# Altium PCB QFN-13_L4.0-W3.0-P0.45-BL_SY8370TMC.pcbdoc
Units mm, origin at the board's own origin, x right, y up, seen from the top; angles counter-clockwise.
Board outline 17.4 x 16.65 mm, 2 copper layers (Top Layer, Bottom Layer), stack 0 mm thick; 1 components, 0 nets, 13 pads, 0 vias.
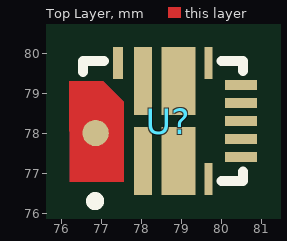
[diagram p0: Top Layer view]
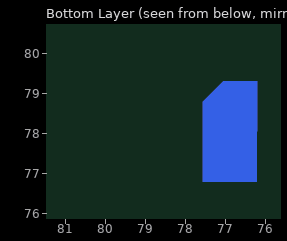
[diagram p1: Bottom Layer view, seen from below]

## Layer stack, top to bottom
Top Layer: signal copper (thickness not stored)
Bottom Layer: signal copper (thickness not stored)

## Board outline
87.25,69.85 69.85,69.85 69.85,86.5 87.25,86.5

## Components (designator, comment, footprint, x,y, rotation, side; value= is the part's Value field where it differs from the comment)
U? "" QFN-13_L4.0-W3.0-P0.45-BL_SY8370TMC 78.69,78.3 r0 top

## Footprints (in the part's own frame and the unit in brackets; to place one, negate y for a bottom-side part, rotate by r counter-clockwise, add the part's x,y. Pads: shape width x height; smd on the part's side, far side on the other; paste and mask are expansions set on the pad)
QFN-13_L4.0-W3.0-P0.45-BL_SY8370TMC [mm]
  round 0.657 smd: 1(-1.828,-0.298)
  rect 0.45x1.7 smd paste+0 mask+0.05: 2(-0.64,-1) 12(-0.64,1)
  rect 0.85x1.7 smd paste+0 mask+0.05: 3(0.24,-1) 11(0.24,1)
  rect 0.2x0.8 smd paste+0 mask+0.05: 4(0.99,-1.45) 10(0.99,1.45)
  rect 0.8x0.25 smd paste+0 mask+0.05: 5(1.81,-0.9) 6(1.81,-0.45) 7(1.81,0) 8(1.81,0.45) 9(1.81,0.9)
  rect 0.25x0.8 smd paste+0 mask+0.05: 13(-1.265,1.45)
  Top Layer region: -2.48,-1.51 -2.49,1 -1.64,1 -1.13,0.49 -1.13,-1.51 -2.48,-1.515
  Bottom Layer region: -2.48,-1.51 -2.49,1 -1.64,1 -1.13,0.49 -1.13,-1.51 -2.48,-1.515
  Multi-Layer region: -2.48,-1.51 -2.49,1 -1.64,1 -1.13,0.49 -1.13,-1.51 -2.48,-1.515
  silkscreen extent -2.14,-2.1 1.86,1.5

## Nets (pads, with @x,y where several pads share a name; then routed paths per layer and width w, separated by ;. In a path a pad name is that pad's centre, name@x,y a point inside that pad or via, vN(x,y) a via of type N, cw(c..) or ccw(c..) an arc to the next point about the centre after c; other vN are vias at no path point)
pads on no net: U?.1 U?.2 U?.3 U?.4 U?.5 U?.6 U?.7 U?.8 U?.9 U?.10 U?.11 U?.12 U?.13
